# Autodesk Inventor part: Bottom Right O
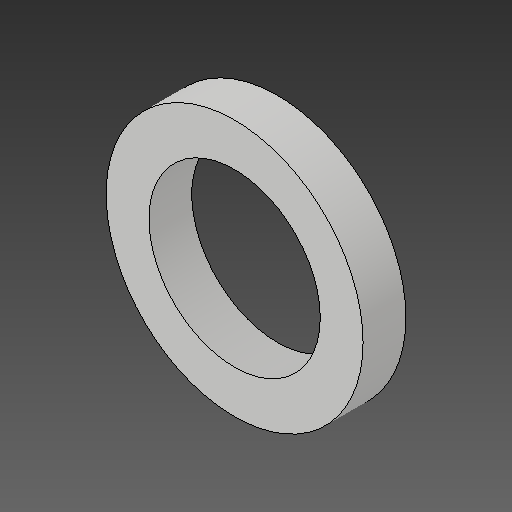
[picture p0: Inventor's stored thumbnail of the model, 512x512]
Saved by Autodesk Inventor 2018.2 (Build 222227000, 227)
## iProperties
Created: 2018-03
Part Number: Bottom Right O
Material: Generic
Document SubType Name: Modeling
Designer: PeterMaxwell-Stewart
Mass: 1.9635 g
Surface Area: 15.708 cm^2
Volume: 1.9635 cm^3
Density: 1 g/cm^3
Appearance: Default
Author: PeterMaxwell-Stewart
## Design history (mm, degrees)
derived "O's and X's.ipt"
feature "Bottom Right O::O's and X's.ipt" dims "d0" = 10
tag "TaggingFeature1"
body "Solid1"
